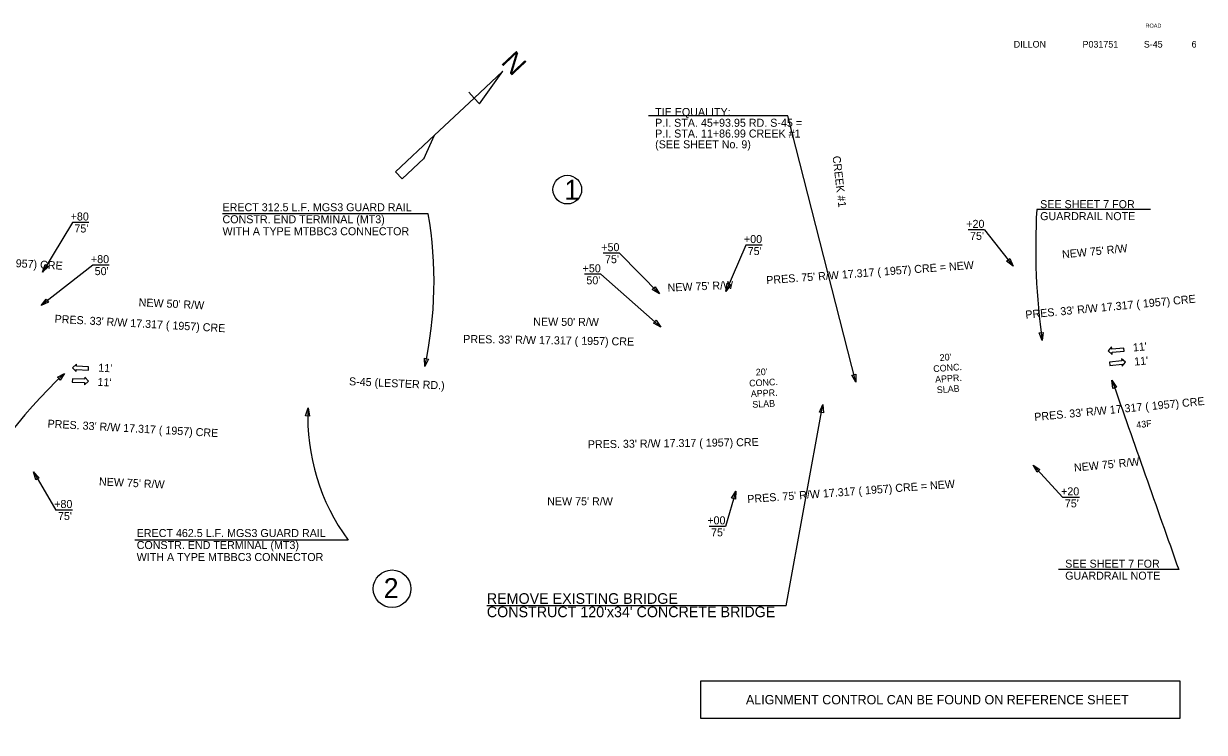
# Model space of a CAD drawing. Extents: x -3336 to 3318, y -3606 to 6276.
# Drawn here: x 683 to 1568, y -5 to 526 of the extents above; entities that cross this region are included whole.
import ezdxf

# ---------------------------------------------------------------- set-up
doc = ezdxf.new("R2010")
doc.units = 0
for name, color, linetype in [('RD_EX_DV_TX_Prop', 7, 'Continuous'), ('RD_EX_Misc', 7, 'Continuous'), ('RD_EX_RW_TX', 7, 'Continuous'), ('RD_HC_Data', 7, 'Continuous'), ('RD_PD_CstnLmt_TX', 7, 'Continuous'), ('RD_PD_Driveway_TX', 7, 'Continuous'), ('RD_PD_Final_LnLine', 7, 'Continuous'), ('RD_PD_Final_TX', 7, 'Continuous'), ('RD_PD_RW', 7, 'Continuous'), ('RD_PD_RW_TX', 7, 'Continuous'), ('RD_SHT_TX', 7, 'Continuous'), ('RD_Sketch1', 7, 'Continuous'), ('RD_TX_Drainage', 7, 'Continuous'), ('RD_TX_Misc1', 7, 'Continuous'), ('RD_TX_RoadID', 7, 'Continuous')]:
    doc.layers.add(name, color=color, linetype=linetype)

msp = doc.modelspace()

# ---------------------------------------------------------------- linework, layer by layer
at = {"layer": 'RD_EX_DV_TX_Prop'}
for centre, radius in [((1090.71, 401.65), 10.77), ((959.29, 102.25), 14.09)]:
    msp.add_circle(centre, radius, dxfattribs=at)
at = {"layer": 'RD_EX_Misc'}
for p, q in [((1042.4, 490.48), (1020.94, 470.37)), ((1024.96, 466.08), (1042.4, 490.48)), ((1042.4, 490.48), (1042.4, 490.48)), ((991.17, 442.48), (1020.94, 470.37)), ((1016.92, 474.67), (1020.94, 470.37)), ((1020.94, 470.37), (1024.96, 466.08)), ((1024.96, 466.08), (1025.22, 466.32)), ((991.17, 442.48), (961.94, 415.09)), ((983.06, 424.81), (991.17, 442.48)), ((966.97, 409.73), (983.21, 424.95)), ((983.21, 424.95), (983.06, 424.81)), ((961.94, 415.09), (966.97, 409.73))]:
    msp.add_line(p, q, dxfattribs=at)
at = {"layer": 'RD_HC_Data'}
for p, q in [((1256.07, 456.89), (1151.6, 456.89)), ((1307.11, 257.1), (1256.07, 456.89))]:
    msp.add_line(p, q, dxfattribs=at)
at = {"layer": 'RD_PD_Final_LnLine'}
for points in [[(1508.38, 280.43), (1508.18, 282.83), (1499.04, 282.07), (1498.91, 283.69), (1496.32, 280.64), (1499.38, 278.05), (1499.24, 279.68)], [(1497.36, 272.23), (1497.62, 269.84), (1506.74, 270.83), (1506.92, 269.21), (1509.42, 272.33), (1506.31, 274.84), (1506.48, 273.22)], [(731.63, 266.24), (731.75, 268.64), (722.59, 269.13), (722.68, 270.75), (719.71, 268.08), (722.38, 265.1), (722.47, 266.73)], [(719.6, 259.6), (719.53, 257.2), (728.7, 256.95), (728.65, 255.32), (731.56, 258.07), (728.81, 260.98), (728.77, 259.35)]]:
    msp.add_lwpolyline(points, close=True, dxfattribs=at)
at = {"layer": 'RD_PD_Final_TX'}
for q in [(1282.37, 240.38), (1030.38, 89.45)]:
    msp.add_line((1254.92, 89.45), q, dxfattribs=at)
for centre, radius, start, end in [((971.12, -12.76), 377.79, 132.93359, 174.61878), ((1633.55, 337.29), 1085.16, 196.85399, 213.14949)]:
    msp.add_arc(centre, radius, start, end, dxfattribs=at)
at = {"layer": 'RD_PD_RW'}
for p, q in [((719.63, 377), (697.29, 339.68)), ((732, 377), (719.63, 377)), ((1403.64, 371.47), (1391.27, 371.47)), ((1403.64, 371.47), (1425.03, 344.27)), ((1224.54, 360.07), (1209.72, 325.35)), ((1236.91, 360.07), (1224.54, 360.07)), ((1129.91, 353.97), (1117.54, 353.97)), ((1129.91, 353.97), (1159.75, 323.5)), ((734.83, 345.02), (696.13, 314.71)), ((747.2, 345.02), (734.83, 345.02)), ((1115.92, 338.13), (1103.55, 338.13)), ((1115.92, 338.13), (1160.98, 298.52)), ((1440.02, 195.02), (1462.34, 170.81)), ((690.34, 189.85), (707.3, 161.32)), ((1217.08, 175.53), (1209.42, 149.07)), ((1474.72, 170.81), (1462.34, 170.81)), ((719.67, 161.32), (707.3, 161.32)), ((1209.42, 149.07), (1197.05, 149.07))]:
    msp.add_line(p, q, dxfattribs=at)
at = {"layer": 'RD_Sketch1'}
msp.add_lwpolyline([(1190.84, 33.25), (1550, 33.25), (1550, 4.86), (1190.84, 4.86)], close=True, dxfattribs=at)
at = {"layer": 'RD_TX_Drainage'}
for points in [[(701.66, 344.06), (697.29, 339.68), (699.08, 345.6)], [(1422.5, 349.91), (1425.03, 344.27), (1420.14, 348.06)], [(1156.63, 328.84), (1159.75, 323.5), (1154.48, 326.74)], [(1213.45, 330.28), (1209.72, 325.35), (1210.69, 331.46)], [(701.78, 317.23), (696.13, 314.71), (699.93, 319.59)], [(1157.46, 303.61), (1160.98, 298.52), (1155.48, 301.36)], [(1447.51, 294.55), (1446.86, 288.4), (1444.54, 294.13)], [(986.59, 274.46), (983.83, 268.92), (983.67, 275.11)], [(708.38, 260.85), (713.79, 263.84), (710.42, 258.65)], [(1307.07, 263.29), (1307.11, 257.1), (1304.17, 262.54)], [(1499.74, 252.59), (1499.17, 258.75), (1502.58, 253.59)], [(1279.82, 234.74), (1282.37, 240.38), (1282.77, 234.21)], [(894.51, 231.92), (896.28, 237.85), (897.5, 231.79)], [(1442.99, 189.59), (1440.02, 195.02), (1445.19, 191.62)], [(692.11, 183.92), (690.34, 189.85), (694.69, 185.45)], [(1213.97, 170.19), (1217.08, 175.53), (1216.85, 169.35)]]:
    msp.add_lwpolyline(points, close=True, dxfattribs=at)
at = {"layer": 'RD_TX_Misc1'}
for p, q in [((986.4, 383.6), (832.16, 383.6)), ((1528, 386.68), (1442.75, 386.68)), ((926.41, 138.75), (766.47, 138.75)), ((1549.21, 116.6), (1459.1, 116.6))]:
    msp.add_line(p, q, dxfattribs=at)
for centre, radius, start, end in [((696.36, 332.75), 294.47, 347.48254, 9.94484), ((1945.9, 358.53), 503.94, 176.79771, 188.00013), ((107240.14, 37397.98), 112073.52, 199.3527248, 199.4297669), ((1051.26, 230.84), 155.14, 177.40927, 216.41236)]:
    msp.add_arc(centre, radius, start, end, dxfattribs=at)

# ---------------------------------------------------------------- texts
at = {"layer": 'RD_EX_DV_TX_Prop'}
for s, p in [('1', (1088.52, 394.02)), ('2', (953.03, 95.21))]:
    msp.add_text(s, height=15, dxfattribs=at).set_placement(p)
at = {"layer": 'RD_EX_Misc'}
msp.add_text('N', height=15, rotation=313.13622, dxfattribs=at).set_placement((1040.38, 496.7))
at = {"layer": 'RD_EX_RW_TX'}
for s, rotation, p in [("PRES. 75' R/W 17.317 ( 1957) CRE", 356.78607, (584.16, 348.73)), ("PRES. 75' R/W 17.317 ( 1957) CRE = NEW", 4.24816, (1240.14, 330.72)), ("PRES. 33' R/W 17.317 ( 1957) CRE", 5.39841, (1434.53, 304.84)), ("PRES. 33' R/W 17.317 ( 1957) CRE ", 356.78607, (706.12, 301.84)), ("PRES. 33' R/W 17.317 ( 1957) CRE ", 359.09824, (1012.63, 286.67)), ("PRES. 33' R/W 17.317 ( 1957) CRE", 5.39841, (1441.2, 228.1)), ("PRES. 33' R/W 17.317 ( 1957) CRE", 356.78607, (700.84, 223.19)), ("PRES. 33' R/W 17.317 ( 1957) CRE", 0.77912, (1106.16, 207.6)), ("PRES. 75' R/W 17.317 ( 1957) CRE = NEW", 4.24816, (1225.94, 166.49))]:
    msp.add_text(s, height=6, rotation=rotation, dxfattribs=at).set_placement(p)
at = {"layer": 'RD_HC_Data'}
for s, p in [('TIE EQUALITY:', (1156.6, 456.89)), ('P.I. STA. 45+93.95 RD. S-45 =', (1156.6, 448.81)), ('P.I. STA. 11+86.99 CREEK #1', (1156.6, 440.73)), ('(SEE SHEET No. 9)', (1156.6, 432.65))]:
    msp.add_text(s, height=6, dxfattribs=at).set_placement(p)
at = {"layer": 'RD_PD_CstnLmt_TX'}
msp.add_text('43F', height=5, rotation=5.73692, dxfattribs=at).set_placement((1517.65, 222.7))
at = {"layer": 'RD_PD_Driveway_TX'}
for rotation, p in [(5.13984, (1515.14, 280.23)), (5.13984, (1516.09, 269.63)), (357.04189, (738.85, 265.14)), (357.04189, (738.3, 254.51))]:
    msp.add_text("11'", height=6, rotation=rotation, dxfattribs=at).set_placement(p)
at = {"layer": 'RD_PD_Final_TX'}
for s, rotation, p in [("20'", 4.16869, (1370.16, 273.1)), ("20'", 3.04117, (1232.23, 262.17)), ('CONC.', 4.16869, (1365.33, 264.73)), ('CONC.', 3.04117, (1227.23, 253.9)), ('APPR.', 4.16869, (1366.72, 256.81)), ('APPR.', 3.04117, (1228.46, 245.95)), ('SLAB', 4.16869, (1368, 248.88)), ('SLAB', 3.04117, (1229.58, 238))]:
    msp.add_text(s, height=5, rotation=rotation, dxfattribs=at).set_placement(p)
for s, p in [('REMOVE EXISTING BRIDGE', (1030.38, 90.92)), ("CONSTRUCT 120'x34' CONCRETE BRIDGE", (1030.38, 80.92))]:
    msp.add_text(s, height=8, dxfattribs=at).set_placement(p)
at = {"layer": 'RD_PD_RW'}
for s, p in [('+80', (718.29, 378.5)), ("75'", (721.11, 369.5)), ('+20', (1389.93, 372.97)), ('+00', (1223.21, 361.57)), ("75'", (1392.75, 363.97)), ('+50', (1116.2, 355.47)), ("75'", (1226.02, 352.57)), ('+80', (733.49, 346.52)), ('+50', (1102.21, 339.63)), ("75'", (1119.02, 346.47)), ("50'", (736.31, 337.52)), ("50'", (1105.03, 330.63)), ('+20', (1461.01, 172.31)), ('+80', (705.96, 162.82)), ("75'", (1463.82, 163.31)), ("75'", (708.78, 153.82)), ('+00', (1195.72, 150.57)), ("75'", (1198.53, 141.57))]:
    msp.add_text(s, height=6, dxfattribs=at).set_placement(p)
at = {"layer": 'RD_PD_RW_TX'}
for s, rotation, p in [("NEW 75' R/W", 5.5345, (1462.01, 350.06)), ("NEW 75' R/W", 2.37987, (1166.03, 325.16)), ("NEW 50' R/W", 357.28257, (769.16, 314.21)), ("NEW 50' R/W", 359.82885, (1065.18, 299.54)), ("NEW 75' R/W", 5.5345, (1470.97, 190.08)), ("NEW 75' R/W", 357.28257, (739.43, 179.79)), ("NEW 75' R/W", 359.78445, (1075.62, 164.95))]:
    msp.add_text(s, height=6, rotation=rotation, dxfattribs=at).set_placement(p)
at = {"layer": 'RD_SHT_TX'}
for s, height, p in [('ROAD', 3, (1524.29, 523.15)), ('DILLON', 5, (1425.51, 508.2)), ('P031751', 5, (1477.09, 508.2)), ('S-45', 5, (1523.05, 508.2)), ('6', 5, (1558.88, 508.2))]:
    msp.add_text(s, height=height, dxfattribs=at).set_placement(p)
at = {"layer": 'RD_Sketch1'}
msp.add_text('ALIGNMENT CONTROL CAN BE FOUND ON REFERENCE SHEET', height=7, dxfattribs=at).set_placement((1224.68, 15.55))
at = {"layer": 'RD_TX_Misc1'}
for s, p in [('ERECT 312.5 L.F. MGS3 GUARD RAIL', (832.16, 385.43)), ('SEE SHEET 7 FOR', (1445.33, 387.75)), ('CONSTR. END TERMINAL (MT3)', (832.16, 376.43)), ('GUARDRAIL NOTE', (1445.33, 378.75)), ('WITH A TYPE MTBBC3 CONNECTOR', (832.16, 367.43)), ('ERECT 462.5 L.F. MGS3 GUARD RAIL', (767.81, 141.04)), ('CONSTR. END TERMINAL (MT3)', (767.81, 132.04)), ('WITH A TYPE MTBBC3 CONNECTOR', (767.81, 123.04)), ('SEE SHEET 7 FOR', (1464.1, 118.07)), ('GUARDRAIL NOTE', (1464.1, 109.07))]:
    msp.add_text(s, height=6, dxfattribs=at).set_placement(p)
at = {"layer": 'RD_TX_RoadID'}
for s, rotation, p in [('CREEK #1', 276.71341, (1289.57, 426.62)), ('S-45 (LESTER RD.)', 357.4133, (926.93, 254.94))]:
    msp.add_text(s, height=6, rotation=rotation, dxfattribs=at).set_placement(p)

doc.saveas('drawing.dxf')
